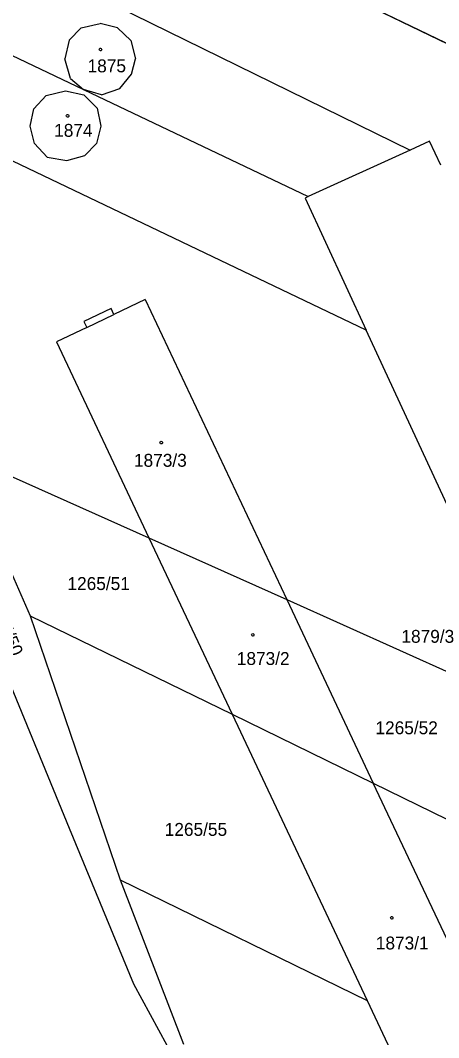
# Model space of a CAD drawing. Extents: x -779618 to -776429, y -1144546 to -1143350.
# Drawn here: x -777222.5 to -777167.4, y -1144114.1 to -1143980.2 of the extents above; entities that cross this region are included whole.
import ezdxf

# ---------------------------------------------------------------- set-up
doc = ezdxf.new("R2010")
doc.units = 0
for name, color, linetype in [('1', 7, 'Continuous'), ('11', 7, 'Continuous'), ('12', 7, 'Continuous'), ('2', 7, 'Continuous'), ('4', 7, 'Continuous'), ('5', 7, 'Continuous'), ('7', 7, 'Continuous')]:
    doc.layers.add(name, color=color, linetype=linetype)

msp = doc.modelspace()

# ---------------------------------------------------------------- linework, layer by layer
at = {"layer": '1'}
for p, q in [((-777258.48, -1143968.19), (-777214.18, -1143989.29)), ((-777214.44, -1143976.01), (-777171.18, -1143997.24)), ((-777182.11, -1143975.59), (-777151.49, -1143990.35)), ((-777214.5, -1143981.16), (-777212.01, -1143980.59)), ((-777209.69, -1143981.14), (-777212.01, -1143980.59)), ((-777216.09, -1143982.78), (-777214.5, -1143981.16)), ((-777207.97, -1143982.81), (-777209.69, -1143981.14)), ((-777216.09, -1143982.78), (-777216.66, -1143985.24)), ((-777207.97, -1143982.81), (-777207.36, -1143985.24)), ((-777176.95, -1144020.96), (-777252.93, -1143984.66)), ((-777215.92, -1143987.82), (-777216.66, -1143985.24)), ((-777207.86, -1143987.26), (-777207.36, -1143985.24)), ((-777209.4, -1143989.12), (-777207.86, -1143987.26)), ((-777215.92, -1143987.82), (-777214.18, -1143989.29)), ((-777220.72, -1143991.8), (-777219.09, -1143990.07)), ((-777219.09, -1143990.07), (-777216.57, -1143989.44)), ((-777216.57, -1143989.44), (-777214.14, -1143989.99)), ((-777214.18, -1143989.29), (-777184.6, -1144003.38)), ((-777211.83, -1143989.97), (-777214.18, -1143989.29)), ((-777212.38, -1143991.73), (-777214.14, -1143989.99)), ((-777211.83, -1143989.97), (-777209.4, -1143989.12)), ((-777221.22, -1143994.09), (-777220.72, -1143991.8)), ((-777212.38, -1143991.73), (-777211.92, -1143994.09)), ((-777220.62, -1143996.4), (-777221.22, -1143994.09)), ((-777211.92, -1143994.09), (-777212.48, -1143996.38)), ((-777218.96, -1143998.16), (-777220.62, -1143996.4)), ((-777212.48, -1143996.38), (-777214.02, -1143997.96)), ((-777168.61, -1143996.07), (-777171.18, -1143997.24)), ((-777167.13, -1143999.23), (-777168.61, -1143996.07)), ((-777218.96, -1143998.16), (-777216.39, -1143998.63)), ((-777216.39, -1143998.63), (-777214.02, -1143997.96)), ((-777171.18, -1143997.24), (-777184.6, -1144003.38)), ((-777184.6, -1144003.38), (-777184.99, -1144003.56)), ((-777184.99, -1144003.56), (-777176.95, -1144020.96)), ((-777206.08, -1144016.93), (-777210.19, -1144018.89)), ((-777206.08, -1144016.93), (-777187.43, -1144056.45)), ((-777210.56, -1144018.11), (-777214.13, -1144019.82)), ((-777210.19, -1144018.89), (-777210.56, -1144018.11)), ((-777213.76, -1144020.59), (-777217.75, -1144022.5)), ((-777214.13, -1144019.82), (-777213.76, -1144020.59)), ((-777163.68, -1144049.68), (-777176.95, -1144020.96)), ((-777217.75, -1144022.5), (-777205.57, -1144048.32)), ((-777230.69, -1144037.07), (-777205.57, -1144048.32)), ((-777230.69, -1144037.07), (-777221.2, -1144058.56)), ((-777205.57, -1144048.32), (-777187.43, -1144056.45)), ((-777205.57, -1144048.32), (-777194.63, -1144071.53)), ((-777216.04, -1144086.59), (-777229.85, -1144053.13)), ((-777187.43, -1144056.45), (-777165.16, -1144066.43)), ((-777187.43, -1144056.45), (-777176.03, -1144080.61)), ((-777221.2, -1144058.56), (-777209.36, -1144093.35)), ((-777221.2, -1144058.56), (-777194.63, -1144071.53)), ((-777194.63, -1144071.53), (-777176.03, -1144080.61)), ((-777194.63, -1144071.53), (-777176.85, -1144109.25)), ((-777176.03, -1144080.61), (-777156.67, -1144090.07)), ((-777158.22, -1144118.36), (-777176.03, -1144080.61)), ((-777207.58, -1144107.1), (-777216.04, -1144086.59)), ((-777209.36, -1144093.35), (-777201.02, -1144114.97)), ((-777209.36, -1144093.35), (-777176.85, -1144109.25)), ((-777183.36, -1144151.49), (-777207.58, -1144107.1)), ((-777176.85, -1144109.25), (-777168.29, -1144127.4))]:
    msp.add_line(p, q, dxfattribs=at)
at = {"layer": '11'}
msp.add_lwpolyline([(-777233.61, -1143950.34), (-777182.11, -1143975.59), (-777151.49, -1143990.35), (-777149.1, -1143989.23), (-777148.68, -1143990.13), (-777144.83, -1143988.32), (-777141.63, -1143995.11), (-777128.13, -1144001.62), (-777129.93, -1143997.79), (-777127.9, -1143996.84), (-777129.57, -1143993.28), (-777118.21, -1143987.96), (-777116.54, -1143991.53), (-777114.5, -1143990.57), (-777103.79, -1144013.4), (-777099.68, -1144015.4), (-777097.63, -1144016.39), (-777109.29, -1143991.28), (-777109.82, -1143985.95), (-777106.25, -1143978.69)], dxfattribs=at)
at = {"layer": '12'}
for p, q in [((-777214.5, -1143981.16), (-777212.01, -1143980.59)), ((-777209.69, -1143981.14), (-777212.01, -1143980.59)), ((-777216.09, -1143982.78), (-777214.5, -1143981.16)), ((-777207.97, -1143982.81), (-777209.69, -1143981.14)), ((-777216.09, -1143982.78), (-777216.66, -1143985.24)), ((-777207.97, -1143982.81), (-777207.36, -1143985.24)), ((-777215.92, -1143987.82), (-777216.66, -1143985.24)), ((-777207.86, -1143987.26), (-777207.36, -1143985.24)), ((-777209.4, -1143989.12), (-777207.86, -1143987.26)), ((-777215.92, -1143987.82), (-777214.18, -1143989.29)), ((-777220.72, -1143991.8), (-777219.09, -1143990.07)), ((-777219.09, -1143990.07), (-777216.57, -1143989.44)), ((-777216.57, -1143989.44), (-777214.14, -1143989.99)), ((-777211.83, -1143989.97), (-777214.18, -1143989.29)), ((-777212.38, -1143991.73), (-777214.14, -1143989.99)), ((-777211.83, -1143989.97), (-777209.4, -1143989.12)), ((-777221.22, -1143994.09), (-777220.72, -1143991.8)), ((-777212.38, -1143991.73), (-777211.92, -1143994.09)), ((-777220.62, -1143996.4), (-777221.22, -1143994.09)), ((-777211.92, -1143994.09), (-777212.48, -1143996.38)), ((-777218.96, -1143998.16), (-777220.62, -1143996.4)), ((-777212.48, -1143996.38), (-777214.02, -1143997.96)), ((-777168.61, -1143996.07), (-777171.18, -1143997.24)), ((-777167.13, -1143999.23), (-777168.61, -1143996.07)), ((-777218.96, -1143998.16), (-777216.39, -1143998.63)), ((-777216.39, -1143998.63), (-777214.02, -1143997.96)), ((-777171.18, -1143997.24), (-777184.6, -1144003.38)), ((-777184.6, -1144003.38), (-777184.99, -1144003.56)), ((-777184.99, -1144003.56), (-777176.95, -1144020.96)), ((-777206.08, -1144016.93), (-777210.19, -1144018.89)), ((-777206.08, -1144016.93), (-777187.43, -1144056.45)), ((-777213.76, -1144020.59), (-777210.19, -1144018.89)), ((-777213.76, -1144020.59), (-777217.75, -1144022.5)), ((-777163.68, -1144049.68), (-777176.95, -1144020.96)), ((-777217.75, -1144022.5), (-777205.57, -1144048.32)), ((-777205.57, -1144048.32), (-777194.63, -1144071.53)), ((-777187.43, -1144056.45), (-777176.03, -1144080.61)), ((-777194.63, -1144071.53), (-777176.85, -1144109.25)), ((-777158.22, -1144118.36), (-777176.03, -1144080.61)), ((-777176.85, -1144109.25), (-777168.29, -1144127.4))]:
    msp.add_line(p, q, dxfattribs=at)
at = {"layer": '4'}
msp.add_line((-777213.76, -1144020.59), (-777210.19, -1144018.89), dxfattribs=at)
at = {"layer": '5'}
for points in [[(-777211.95, -1143983.84), (-777211.85, -1143983.86), (-777211.8, -1143983.95), (-777211.78, -1143984.01), (-777211.8, -1143984.1), (-777211.88, -1143984.17), (-777211.95, -1143984.18), (-777212.04, -1143984.15), (-777212.1, -1143984.09), (-777212.12, -1143984.01), (-777212.1, -1143983.92), (-777212.02, -1143983.85)], [(-777216.28, -1143992.57), (-777216.18, -1143992.59), (-777216.13, -1143992.68), (-777216.11, -1143992.74), (-777216.13, -1143992.83), (-777216.21, -1143992.9), (-777216.28, -1143992.91), (-777216.37, -1143992.88), (-777216.43, -1143992.82), (-777216.45, -1143992.74), (-777216.43, -1143992.65), (-777216.35, -1143992.58)], [(-777203.95, -1144035.6), (-777203.85, -1144035.62), (-777203.8, -1144035.71), (-777203.78, -1144035.77), (-777203.8, -1144035.86), (-777203.88, -1144035.93), (-777203.95, -1144035.94), (-777204.04, -1144035.91), (-777204.1, -1144035.85), (-777204.12, -1144035.77), (-777204.1, -1144035.68), (-777204.02, -1144035.61)], [(-777191.89, -1144060.92), (-777191.79, -1144060.94), (-777191.74, -1144061.03), (-777191.72, -1144061.09), (-777191.74, -1144061.18), (-777191.82, -1144061.25), (-777191.89, -1144061.26), (-777191.98, -1144061.23), (-777192.04, -1144061.17), (-777192.06, -1144061.09), (-777192.04, -1144061), (-777191.96, -1144060.93)], [(-777173.58, -1144098.18), (-777173.48, -1144098.2), (-777173.43, -1144098.29), (-777173.41, -1144098.35), (-777173.43, -1144098.44), (-777173.51, -1144098.51), (-777173.58, -1144098.52), (-777173.67, -1144098.49), (-777173.73, -1144098.43), (-777173.75, -1144098.35), (-777173.73, -1144098.26), (-777173.65, -1144098.19)]]:
    msp.add_lwpolyline(points, close=True, dxfattribs=at)

# ---------------------------------------------------------------- texts
at = {"layer": '2'}
for s, p in [('1875', (-777213.65, -1143987.01)), ('1874', (-777218.05, -1143995.5)), ('1873/3', (-777207.54, -1144038.95)), ('1265/51', (-777216.3, -1144055.18)), ('1873/2', (-777194, -1144065.05)), ('1265/52', (-777175.74, -1144074.17)), ('1265/55', (-777203.49, -1144087.55)), ('1873/1', (-777175.69, -1144102.51))]:
    msp.add_text(s, height=1.7, dxfattribs=at).set_placement(p)
msp.add_text('1265/50', height=1.7, rotation=292.8387, dxfattribs=at).set_placement((-777226.82, -1144056.45))
at = {"layer": '7'}
msp.add_text('1879/3', height=1.7, dxfattribs=at).set_placement((-777172.32, -1144062.13))

doc.saveas('drawing.dxf')
